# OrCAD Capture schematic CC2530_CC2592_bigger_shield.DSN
size Custom; title: CC2530-CC2592 EM; rev: 2.1
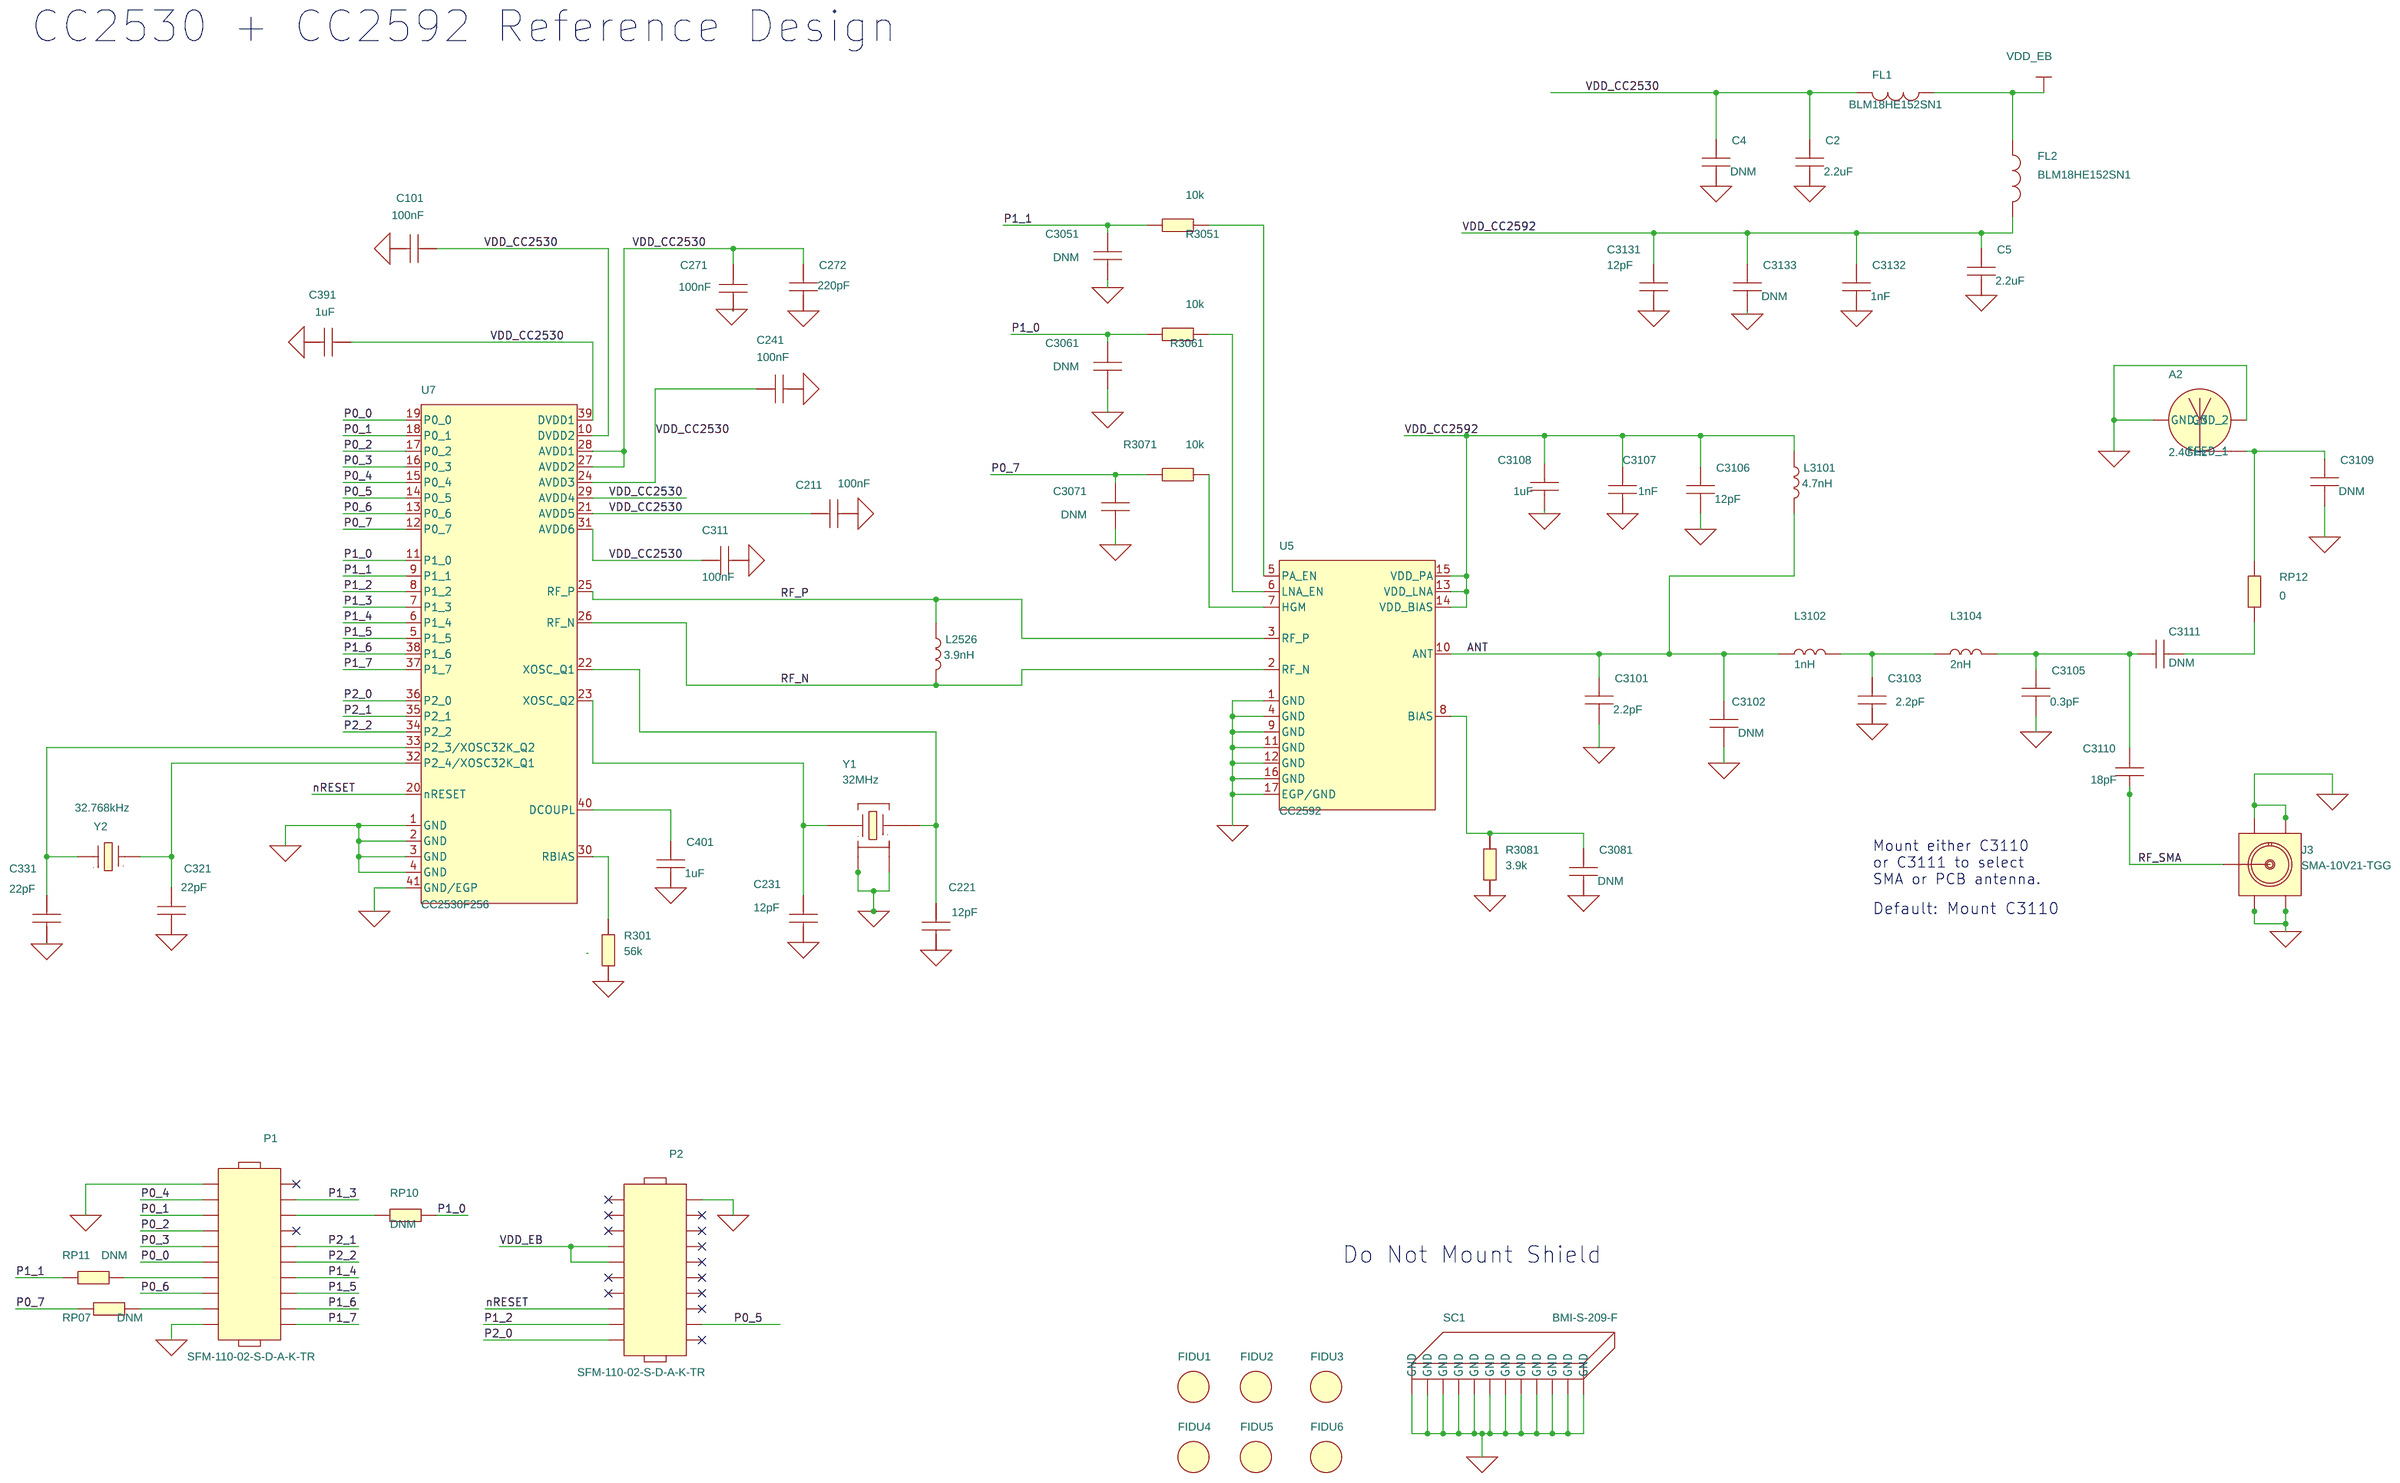
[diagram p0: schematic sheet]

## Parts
A2  2.4GHz  [ANTENNA_DN007AN]
C2  2.2uF  [CAPC1608X90N]
C4  DNM  [CAPC1005X60N]
C5  2.2uF  [CAPC1608X90N]
C101  100nF  [CAPC1005X60N]
C211  100nF  [CAPC1005X60N]
C221  12pF  [CAPC1005X60N]
C231  12pF  [CAPC1005X60N]
C241  100nF  [CAPC1005X60N]
C271  100nF  [CAPC1005X60N]
C272  220pF  [CAPC1005X60N]
C311  100nF  [CAPC1005X60N]
C321  22pF  [CAPC1005X60N]
C331  22pF  [CAPC1005X60N]
C391  1uF  [CAPC1005X60N]
C401  1uF  [CAPC1005X60N]
C3051  DNM  [CAPC1005X60N]
C3061  DNM  [CAPC1005X60N]
C3071  DNM  [CAPC1005X60N]
C3081  DNM  [CAPC1005X60N]
C3101  2.2pF  [CAPC1005X60N]
C3102  DNM  [CAPC1005X60N]
C3103  2.2pF  [CAPC1005X60N]
C3105  0.3pF  [CAPC1005X60N]
C3106  12pF  [CAPC1005X60N]
C3107  1nF  [CAPC1005X60N]
C3108  1uF  [CAPC1005X60N]
C3109  DNM  [CAPC1005X60N]
C3110  18pF  [CAPC1005X60N]
C3111  DNM  [CAPC1005X60N]
C3131  12pF  [CAPC1005X60N]
C3132  1nF  [CAPC1005X60N]
C3133  DNM  [CAPC1005X60N]
FIDU1  FIDU_1MM  [FID100X115]
FIDU2  FIDU_1MM  [FID100X115]
FIDU3  FIDU_1MM  [FID100X115]
FIDU4  FIDU_1MM  [FID100X115]
FIDU5  FIDU_1MM  [FID100X115]
FIDU6  FIDU_1MM  [FID100X115]
FL1  BLM18HE152SN1  [FIL_BLM18HE152SN1DN]
FL2  BLM18HE152SN1  [FIL_BLM18HE152SN1DN]
J3  SMA-10V21-TGG  [HUSTSAN_SMA10V21TGGAN]
L2526  3.9nH  [INDC1005X60N]
L3101  4.7nH  [INDC1005X60N]
L3102  1nH  [INDC1005X60N]
L3104  2nH  [INDC1005X60N]
P1  SFM-110-02-S-D-A-K-TR  [SAMTEC_SFM11002AN]
P2  SFM-110-02-S-D-A-K-TR  [SAMTEC_SFM11002AN]
R301  56k  [RESC1005X40N]
R3051  10k  [RESC1005X40N]
R3061  10k  [RESC1005X40N]
R3071  10k  [RESC1005X40N]
R3081  3.9k  [RESC1005X40N]
RP07  DNM  [RESC1005X40N]
RP10  DNM  [RESC1005X40N]
RP11  DNM  [RESC1005X40N]
RP12  0  [RESC1005X40N]
SC1  BMI-S-209-F  [MECH_BMIS209FN]
U5  CC2592  [QFNFC65P400X400X100-17AN]
U7  CC2530F256  [QFNFC50P600X600X100-41CN]
Y1  32MHz  [XTAL_FA128N]
Y2  32.768kHz  [XTAL_FC12MN]

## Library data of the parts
A2 = ANTENNA_DN007: MECHANIC, 2.4GHz INVERTED F ANTENNA, SMD; AutoDoc File: http://notefied-dynamic-precision.com/DB/Apps/Desktop/Item/Object.aspx?id=85542; Budget Currency: N/A; Budget Price: N/A; Datasheet URL 1: N/A; Datasheet URL 2: http://www.ti.com/lit/an/swru120b/swru120b.pdf; Definied Quality: INDUSTRIAL; Esd Level: HBM 500V; FPLIST: ANTENNA_DN007N,ANTENNA_DN007AN; Last Time Buy: N/A; Lead Time: N/A; MPN: DN007; MPN Status: ACTIVE; MSL: N/A; MTBF: N/A; MTBF Standard: N/A; Manufacturer: TEXAS INSTRUMENTS; Max Oper Temp: +85DEGC; Min Oper Temp: -40DEGC; Mounting Type: SMD; NOTE Status: PREFERRED; Old Footprint: ANTENNA_DN007N,ANTENNA_DN007AN; Packing Size: N/A; Part Number: 13-00347; Part Type: MECHANIC\ANTENNA; Revision: R006; RoHS Status: PART NOT KNOWN; WEIGHT: N/A
C2 C5 = CAPACITOR: CAPACITOR, CERAMIC X5R, 2.2uF, 10V, -20%/+20%, -55DEGC/+85DEGC, 0603, SMD; ALT_SYMBOLS: CAPC1608X90L,CAPC1608X90M; AutoDoc File: http://notefied-dynamic-precision.com/DB/Apps/Desktop/Item/Object.aspx?id=50283; Budget Currency: EUR; Budget Price: 0.067; Datasheet URL 1: http://search.murata.co.jp/Ceramy/image/img/w_hinm/L0005E.pdf; Datasheet URL 2: http://psearch.murata.com/capacitor/product/GRM188R61A225ME34%23.pdf; Definied Quality: INDUSTRIAL; Dielectric Type: X5R; Esd Level: N/A; Last Time Buy: N/A; Lead Time: 20; LifeCycle Status: GROWTH; MPN: GRM188R61A225ME34D; MPN Status: ACTIVE; MSL: 1; MTBF: N/A; MTBF Standard: N/A; Manufacturer: MURATA; Max Oper Temp: +85DEGC; Max Tol: +20%; Min Oper Temp: -55DEGC; Min Tol: -20%; Mounting Type: SMD; NOTE Status: PREFERRED; Old Footprint: CAPC1608X90N,0603; PCB Package: 0603; Packing Size: 4000; Packing Type: TAPE_&_REEL; Part Number: 02-01132; Part Type: CAPACITOR\CERAMIC\0603; Revision: R001; RoHS Status: ROHS_COMPLIANT; Rtd Voltage: 10V; WEIGHT: 0.0063g
C4 C3081 C3102 C3109 C3111 C3133 = CAPACITOR: CAPACITOR, DO NOT MOUNT, 0402, SMD; ALT_SYMBOLS: CAPC1005X60L,CAPC1005X60M; AutoDoc File: https://notefied-dynamic-precision.com/NotefiedWebServices/AutoDocs.aspx?itemid=50472; Old Footprint: CAPC1005X60N,0402; Part Number: 02-01321; Part Type: CAPACITOR\CERAMIC\0402; Revision: R003
C101 C211 C241 C271 C311 = CAPACITOR: CAPACITOR, CERAMIC X7R, 100nF, 6.3V, -10%/+10%, -55DEGC/+125DEGC, 0402, SMD; ALT_SYMBOLS: CAPC1005X60L,CAPC1005X60M; AutoDoc File: http://notefied-dynamic-precision.com/DB/Apps/Desktop/Item/Object.aspx?id=73748; Budget Currency: EUR; Budget Price: 0.004; Datasheet URL 1: http://search.murata.co.jp/Ceramy/image/img/w_hinm/L0005E.pdf; Datasheet URL 2: http://psearch.murata.com/capacitor/product/GRM155R70J104KA01%23.pdf; Definied Quality: INDUSTRIAL; Dielectric Type: X7R; Esd Level: N/A; Last Time Buy: N/A; Lead Time: 6; LifeCycle Status: ACTIVE; MPN: GRM155R70J104KA01D; MPN Status: ACTIVE; MSL: 1; MTBF: N/A; MTBF Standard: N/A; Manufacturer: MURATA; Max Oper Temp: +125DEGC; Max Tol: +10%; Min Oper Temp: -55DEGC; Min Tol: -10%; Mounting Type: SMD; NOTE Status: PREFERRED; Old Footprint: CAPC1005X60N,0402; PCB Package: 0402; Packing Size: 10000; Packing Type: TAPE_&_REEL; Part Number: 02-02323; Part Type: CAPACITOR\CERAMIC\0402; Revision: R000; RoHS Status: ROHS_COMPLIANT; Rtd Voltage: 6.3V; WEIGHT: 0.0016g
C221 C231 C3106 C3131 = CAPACITOR: CAPACITOR, CERAMIC C0G/NP0, 12pF, 50V, -5%/+5%, -55DEGC/+125DEGC, 0402, SMD; ALT_SYMBOLS: CAPC1005X60L,CAPC1005X60M; AutoDoc File: http://notefied-dynamic-precision.com/DB/Apps/Desktop/Item/Object.aspx?id=84867; Budget Currency: EUR; Budget Price: 0.004; Datasheet URL 1: http://search.murata.co.jp/Ceramy/image/img/w_hinm/L0005E.pdf; Datasheet URL 2: http://psearch.murata.com/capacitor/product/GRM1555C1H120JA01%23.pdf; Definied Quality: INDUSTRIAL; Dielectric Type: C0G/NP0; Esd Level: N/A; Last Time Buy: N/A; Lead Time: 10; MPN: GRM1555C1H120JA01D; MPN Status: ACTIVE; MSL: 1; MTBF: N/A; MTBF Standard: N/A; Manufacturer: MURATA; Max Oper Temp: +125DEGC; Max TC: +30PPM/DEGC; Max Tol: +5%; Min Oper Temp: -55DEGC; Min TC: -30PPM/DEGC; Min Tol: -5%; Mounting Type: SMD; NOTE Status: PREFERRED; PCB Package: 0402; Packing Size: 10000; Packing Type: TAPE_&_REEL; Part Number: 02-04168; Part Type: CAPACITOR\CERAMIC\0402; Revision: R000; RoHS Status: ROHS_COMPLIANT; Rtd Voltage: 50V; WEIGHT: 0.0016g
C272 = CAPACITOR: CAPACITOR, CERAMIC C0G/NP0, 220pF, 50V, -5%/+5%, -55DEGC/+125DEGC, 0402, SMD; ALT_SYMBOLS: CAPC1005X60L,CAPC1005X60M; AutoDoc File: http://notefied-dynamic-precision.com/DB/Apps/Desktop/Item/Object.aspx?id=50427; Budget Currency: EUR; Budget Price: 0.005; Datasheet URL 1: http://search.murata.co.jp/Ceramy/image/img/w_hinm/L0005E.pdf; Datasheet URL 2: http://psearch.murata.com/capacitor/product/GRM1555C1H221JA01%23.pdf; Definied Quality: INDUSTRIAL; Dielectric Type: C0G/NP0; Esd Level: N/A; Last Time Buy: N/A; Lead Time: 12; LifeCycle Status: GROWTH; MPN: GRM1555C1H221JA01D; MPN Status: ACTIVE; MSL: 1; MTBF: N/A; MTBF Standard: N/A; Manufacturer: MURATA; Max Oper Temp: +125DEGC; Max Tol: +5%; Min Oper Temp: -55DEGC; Min Tol: -5%; Mounting Type: SMD; NOTE Status: PREFERRED; Old Footprint: CAPC1005X60N,0402; PCB Package: 0402; Packing Size: 10000; Packing Type: TAPE_&_REEL; Part Number: 02-01276; Part Type: CAPACITOR\CERAMIC\0402; Revision: R001; RoHS Status: ROHS_COMPLIANT; Rtd Voltage: 50V; WEIGHT: 0.0016g
C321 C331 = CAPACITOR: CAPACITOR, CERAMIC C0G/NP0, 22pF, 50V, -5%/+5%, -55DEGC/+125DEGC, 0402, SMD; ALT_SYMBOLS: CAPC1005X60L,CAPC1005X60M; AutoDoc File: http://notefied-dynamic-precision.com/DB/Apps/Desktop/Item/Object.aspx?id=86084; Budget Currency: EUR; Budget Price: 0.007; Datasheet URL 1: http://search.murata.co.jp/Ceramy/image/img/w_hinm/L0005E.pdf; Datasheet URL 2: http://psearch.murata.com/capacitor/product/GRM1555C1H220JA01%23.pdf; Definied Quality: INDUSTRIAL; Dielectric Type: C0G/NP0; Esd Level: N/A; Last Time Buy: N/A; Lead Time: 12; MPN: GRM1555C1H220JA01D; MPN Status: ACTIVE; MSL: 1; MTBF: N/A; MTBF Standard: N/A; Manufacturer: MURATA; Max Oper Temp: +125DEGC; Max Tol: +5%; Min Oper Temp: -55DEGC; Min Tol: -5%; Mounting Type: SMD; NOTE Status: PREFERRED; PCB Package: 0402; Packing Size: 10000; Packing Type: TAPE_&_REEL; Part Number: 02-04373; Part Type: CAPACITOR\CERAMIC\0402; Revision: R003; RoHS Status: ROHS_COMPLIANT; Rtd Voltage: 50V; WEIGHT: 0.0016g
C391 C401 C3108 = CAPACITOR: CAPACITOR, CERAMIC X5R, 1uF, 10V, -10%/+10%, -55DEGC/+85DEGC, 0402, SMD; ALT_SYMBOLS: CAPC1005X60L,CAPC1005X60M; AutoDoc File: http://notefied-dynamic-precision.com/DB/Apps/Desktop/Item/Object.aspx?id=74236; Budget Currency: EUR; Budget Price: 0.016; Datasheet URL 1: http://search.murata.co.jp/Ceramy/image/img/w_hinm/L0005E.pdf; Datasheet URL 2: http://psearch.murata.com/capacitor/product/GRM155R61A105KE15%23.pdf; Definied Quality: INDUSTRIAL; Dielectric Type: X5R; Esd Level: N/A; Last Time Buy: N/A; Lead Time: 14; MPN: GRM155R61A105KE15D; MPN Status: ACTIVE; MSL: 1; MTBF: N/A; MTBF Standard: N/A; Manufacturer: MURATA; Max Oper Temp: +85DEGC; Max Tol: +10%; Min Oper Temp: -55DEGC; Min Tol: -10%; Mounting Type: SMD; NOTE Status: PREFERRED; Old Footprint: CAPC1005X60N,0402; PCB Package: 0402; Packing Size: 10000; Packing Type: TAPE_&_REEL; Part Number: 02-02381; Part Type: CAPACITOR\CERAMIC\0402; Revision: R002; RoHS Status: ROHS_COMPLIANT; Rtd Voltage: 10V; WEIGHT: 0.0016g
C3051 C3061 C3071 = CAPACITOR: CAPACITOR, DO NOT MOUNT, 0402, SMD; ALT_SYMBOLS: CAPC1005X60L,CAPC1005X60M; AutoDoc File: http://notefied-dynamic-precision.com/DB/Apps/Desktop/Item/Object.aspx?id=50472; Old Footprint: CAPC1005X60N,0402; Part Number: 02-01321; Part Type: CAPACITOR\CERAMIC\0402; Revision: R003
C3101 = CAPACITOR: CAPACITOR, CERAMIC C0G/NP0, 2.2pF, 50V, -0.25pF/+0.25pF, -55DEGC/+125DEGC, 0402, SMD; ALT_SYMBOLS: CAPC1005X60L,CAPC1005X60M; AutoDoc File: http://notefied-dynamic-precision.com/DB/Apps/Desktop/Item/Object.aspx?id=87251; Budget Currency: EUR; Budget Price: 0.006; Datasheet URL 1: http://search.murata.co.jp/Ceramy/image/img/w_hinm/L0005E.pdf; Datasheet URL 2: http://psearch.murata.com/capacitor/product/GRM1555C1H2R2CA01%23.pdf; Definied Quality: INDUSTRIAL; Dielectric Type: C0G/NP0; Esd Level: N/A; Last Time Buy: N/A; Lead Time: 12; MPN: GRM1555C1H2R2CA01D; MPN Status: ACTIVE; MSL: 1; MTBF: N/A; MTBF Standard: N/A; Manufacturer: MURATA; Max Oper Temp: +125DEGC; Max Tol: +0.25pF; Min Oper Temp: -55DEGC; Min Tol: -0.25pF; Mounting Type: SMD; NOTE Status: PREFERRED; PCB Package: 0402; Packing Size: 10000; Packing Type: TAPE_&_REEL; Part Number: 02-04605; Part Type: CAPACITOR\CERAMIC\0402; Revision: R001; RoHS Status: ROHS_COMPLIANT; Rtd Voltage: 50V; WEIGHT: 0.0016g
C3103 = CAPACITOR: CAPACITOR, CERAMIC C0G/NP0, 2.2pF, 50V, -0.25pF/+0.25pF, -55DEGC/+125DEGC, 0402, SMD; ALT_SYMBOLS: CAPC1005X60L,CAPC1005X60M; AutoDoc File: http://notefied-dynamic-precision.com/DB/Apps/Desktop/Item/Object.aspx?id=87251; Budget Currency: EUR; Budget Price: 0.005; Datasheet URL 1: http://search.murata.co.jp/Ceramy/image/img/w_hinm/L0005E.pdf; Datasheet URL 2: http://psearch.murata.com/capacitor/product/GRM1555C1H2R2CA01%23.pdf; Definied Quality: INDUSTRIAL; Dielectric Type: C0G/NP0; Esd Level: N/A; Last Time Buy: N/A; Lead Time: 12; MPN: GRM1555C1H2R2CA01D; MPN Status: ACTIVE; MSL: 1; MTBF: N/A; MTBF Standard: N/A; Manufacturer: MURATA; Max Oper Temp: +125DEGC; Max Tol: +0.25pF; Min Oper Temp: -55DEGC; Min Tol: -0.25pF; Mounting Type: SMD; NOTE Status: PREFERRED; PCB Package: 0402; Packing Size: 10000; Packing Type: TAPE_&_REEL; Part Number: 02-04605; Part Type: CAPACITOR\CERAMIC\0402; Revision: R001; RoHS Status: ROHS_COMPLIANT; Rtd Voltage: 50V; WEIGHT: 0.0016g
C3105 = CAPACITOR: CAPACITOR, CERAMIC C0G/NP0, 0.3pF, 50V, -0.1pF/+0.1pF, -55DEGC/+125DEGC, 0402, SMD; ALT_SYMBOLS: CAPC1005X60L,CAPC1005X60M; AutoDoc File: http://notefied-dynamic-precision.com/DB/Apps/Desktop/Item/Object.aspx?id=90889; Budget Currency: EUR; Budget Price: 0.014; Datasheet URL 1: http://search.murata.co.jp/Ceramy/image/img/w_hinm/L0005E.pdf; Datasheet URL 2: http://psearch.murata.com/capacitor/product/GRM1555C1HR30BA01%23.pdf; Definied Quality: INDUSTRIAL; Dielectric Type: C0G/NP0; Esd Level: N/A; Last Time Buy: N/A; Lead Time: 10; MPN: GRM1555C1HR30BA01D; MPN Status: ACTIVE; MSL: N/A; MTBF: N/A; MTBF Standard: N/A; Manufacturer: MURATA; Max Oper Temp: +125DEGC; Max TC: +30PPM/DEGC; Max Tol: +0.1pF; Min Oper Temp: -55DEGC; Min TC: -30PPM/DEGC; Min Tol: -0.1pF; Mounting Type: SMD; NOTE Status: PREFERRED; PCB Package: 0402; Packing Size: 10000; Packing Type: TAPE_&_REEL; Part Number: 02-05036; Part Type: CAPACITOR\CERAMIC\0402; Revision: R001; RoHS Status: ROHS_COMPLIANT; Rtd Voltage: 50V; WEIGHT: 0.0016g
C3107 = CAPACITOR: CAPACITOR, CERAMIC C0G/NP0, 1nF, 50V, -5%/+5%, -55DEGC/+125DEGC, 0402, SMD; ALT_SYMBOLS: CAPC1005X60L,CAPC1005X60M; AutoDoc File: http://notefied-dynamic-precision.com/DB/Apps/Desktop/Item/Object.aspx?id=88013; Budget Currency: USD; Budget Price: 0.00589; Datasheet URL 1: N/A; Datasheet URL 2: N/A; Definied Quality: INDUSTRIAL; Dielectric Type: C0G/NP0; Esd Level: N/A; Last Time Buy: N/A; Lead Time: N/A; MPN: CAPACITOR_0402_1nF_C0G/NP0_M_+/-5%_50V; MPN Status: ACTIVE; MSL: N/A; MTBF: N/A; MTBF Standard: N/A; Manufacturer: MANUFACTURER SELECTION; Max Oper Temp: +125DEGC; Max Tol: +5%; Min Oper Temp: -55DEGC; Min Tol: -5%; Mounting Type: SMD; NOTE Status: PREFERRED; PCB Package: 0402; Packing Size: 10000; Packing Type: TAPE_&_REEL; Part Number: 02-04728; Part Type: CAPACITOR\CERAMIC\0402; Revision: R001; RoHS Status: ROHS_COMPLIANT; Rtd Voltage: 50V; WEIGHT: N/A
C3110 = CAPACITOR: CAPACITOR, CERAMIC C0G/NPO, 18pF, 50V, -55DEGC/+125DEGC, 0402, SMD; ALT_SYMBOLS: CAPC1005X60L,CAPC1005X60M; AutoDoc File: http://notefied-dynamic-precision.com/DB/Apps/Desktop/Item/Object.aspx?id=74533; Budget Currency: USD; Budget Price: 0.0051; Datasheet URL 1: http://search.murata.co.jp/Ceramy/image/img/w_hinm/L0005E.pdf; Datasheet URL 2: http://psearch.murata.com/capacitor/product/GRM1555C1H180JA01%23.pdf; Definied Quality: INDUSTRIAL; Dielectric Type: C0G/NP0; Esd Level: N/A; Last Time Buy: N/A; Lead Time: 10; MPN: GRM1555C1H180JA01D; MPN Status: ACTIVE; MSL: 1; MTBF: N/A; MTBF Standard: N/A; Manufacturer: MURATA; Max Oper Temp: +125DEGC; Max Tol: +5%; Min Oper Temp: -55DEGC; Min Tol: -5%; Mounting Type: SMD; NOTE Status: PREFERRED; PCB Package: 0402; Packing Size: 10000; Packing Type: TAPE_&_REEL; Part Number: 02-02407; Part Type: CAPACITOR\CERAMIC\0402; Revision: R002; RoHS Status: ROHS_COMPLIANT; Rtd Voltage: 50V; WEIGHT: 0.0016g
C3132 = CAPACITOR: CAPACITOR, CERAMIC X7R, 1nF, 50V, -5%/+5%, -55DEGC/+125DEGC, 0402, SMD; ALT_SYMBOLS: CAPC1005X60L,CAPC1005X60M; AutoDoc File: http://notefied-dynamic-precision.com/DB/Apps/Desktop/Item/Object.aspx?id=80112; Budget Currency: USD; Budget Price: 0.00589; Datasheet URL 1: N/A; Datasheet URL 2: N/A; Definied Quality: INDUSTRIAL; Dielectric Type: X7R; Esd Level: N/A; Last Time Buy: N/A; Lead Time: N/A; LifeCycle Status: ACTIVE; MPN: CAPACITOR_0402_1nF_X7R_M_+/-5%_50V; MPN Status: ACTIVE; MSL: N/A; MTBF: N/A; MTBF Standard: N/A; Manufacturer: MANUFACTURER SELECTION; Max Oper Temp: +125DEGC; Max Tol: +5%; Min Oper Temp: -55DEGC; Min Tol: -5%; Mounting Type: SMD; NOTE Status: PREFERRED; PCB Package: 0402; Packing Size: 10000; Packing Type: TAPE_&_REEL; Part Number: 02-03019; Part Type: CAPACITOR\CERAMIC\0402; Revision: R001; RoHS Status: ROHS_COMPLIANT; Rtd Voltage: 50V; WEIGHT: N/A
FIDU1-FIDU6 = FIDMARK: FIDUCIAL MARK, ROUND 1MM; AutoDoc File: http://notefied-dynamic-precision.com/DB/Apps/Desktop/Item/Object.aspx?id=74548; Part Number: 19-00111; Part Type: NON_COMPONENT\FIDUCIAL; Revision: R001
FL1 FL2 = FILTER_2PIN: FILTER, EMI, 1500@100MHz, -55DEGC/+125DEGC, 0603, SMD; ALT_SYMBOLS: FIL_BLM18HE152SN1DL,FIL_BLM18HE152SN1DM; AutoDoc File: http://notefied-dynamic-precision.com/DB/Apps/Desktop/Item/Object.aspx?id=85575; Budget Currency: EUR; Budget Price: 0.165; Datasheet URL 1: http://search.murata.co.jp/Ceramy/image/img/w_hinm/L0110E.pdf; Datasheet URL 2: http://search.murata.co.jp/Ceramy/image/img/PDF/ENG/L0110S0101BLM18H.pdf; Definied Quality: INDUSTRIAL; Esd Level: N/A; Impedance: 1500@100MHz; Last Time Buy: N/A; Lead Time: 10; MPN: BLM18HE152SN1D; MPN Status: ACTIVE; MSL: N/A; MTBF: N/A; MTBF Standard: N/A; Manufacturer: MURATA; Max Oper Temp: +125DEGC; Max Tol: +25%; Min Oper Temp: -55DEGC; Min Tol: -25%; Mounting Type: SMD; NOTE Status: PREFERRED; PCB Package: 0603; Packing Size: 4000; Packing Type: TAPE_&_REEL; Part Number: 04-00470; Part Type: FILTER\EMI\0603; Revision: R001; RoHS Status: ROHS_COMPLIANT; Rtd Current: 0.5A; WEIGHT: 0.006g
J3 = CONN_COAX_1+4: CONNECTOR, COAX RF, STRAIGHT, FEMALE, 1 PIN, SMD; ALT_SYMBOLS: HUSTSAN_SMA10V21TGGL,HUSTSAN_SMA10V21TGGM; AutoDoc File: http://notefied-dynamic-precision.com/DB/Apps/Desktop/Item/Object.aspx?id=84956; Budget Currency: USD; Budget Price: 1.21; Datasheet URL 1: N/A; Datasheet URL 2: http://www.hustsan.com.tw/uploaddir/product/SMA-10V21.pdf; Definied Quality: COMMERCIAL; Esd Level: N/A; FPLIST: HUSTSAN_SMA10V21TGGAN,HUSTSAN_SMA10V21TGGN; Last Time Buy: N/A; Lead Time: 5; MPN Status: ACTIVE; MSL: N/A; MTBF: N/A; MTBF Standard: N/A; Manufacturer: HUS-TSAN; Mounting Type: SMD; NOTE Status: PREFERRED; No Of Pos: 1; Old Footprint: HUSTSAN_SMA10V21TGGAN,HUSTSAN_SMA10V21TGGN; Packing Size: 350; Packing Type: TAPE_&_REEL; Part Number: 06-02188; Part Type: CONNECTOR\COAX; Revision: R003; RoHS Status: ROHS_COMPLIANT; WEIGHT: N/A
L2526 = INDUCTOR: INDUCTOR, CHIP, 3.9nH, -0.3nH/+0.3nH, 0.3A, -55DEGC/+125DEGC, 0402, SMD; ALT_SYMBOLS: INDC1005X60L,INDC1005X60M; AutoDoc File: http://notefied-dynamic-precision.com/DB/Apps/Desktop/Item/Object.aspx?id=87734; Budget Currency: EUR; Budget Price: 0.024; Datasheet URL 1: N/A; Datasheet URL 2: http://psearch.murata.com/inductor/product/LQG15HS3N9S02%23.pdf; Definied Quality: INDUSTRIAL; Esd Level: N/A; Frequency: 6GHz; Last Time Buy: N/A; Lead Time: 9; MPN: LQG15HS3N9S02D; MPN Status: ACTIVE; MSL: N/A; MTBF: N/A; MTBF Standard: N/A; Manufacturer: MURATA; Max Oper Temp: +125DEGC; Max Tol: +0.3nH; Min Oper Temp: -55DEGC; Min Tol: -0.3nH; Mounting Type: SMD; NOTE Status: PREFERRED; PCB Package: 0402; Packing Size: 10000; Packing Type: TAPE_&_REEL; Part Number: 03-06630; Part Type: INDUCTOR\CHIP\0402; Resistance: 0.18; Revision: R001; RoHS Status: ROHS_COMPLIANT; Rtd Current: 0.3A; WEIGHT: 0.001g
L3101 = INDUCTOR: INDUCTOR, CHIP, 4.7nH, -0.3nH/+0.3nH, 0.3A, -55DEGC/+125DEGC, 0402, SMD; ALT_SYMBOLS: INDC1005X60L,INDC1005X60M; AutoDoc File: http://notefied-dynamic-precision.com/DB/Apps/Desktop/Item/Object.aspx?id=87735; Budget Currency: EUR; Budget Price: 0.024; Datasheet URL 1: N/A; Datasheet URL 2: http://psearch.murata.com/inductor/product/LQG15HS4N7S02%23.pdf; Definied Quality: INDUSTRIAL; Esd Level: N/A; Frequency: 6GHz; Last Time Buy: N/A; Lead Time: 9; MPN: LQG15HS4N7S02D; MPN Status: NRND; MSL: N/A; MTBF: N/A; MTBF Standard: N/A; Manufacturer: MURATA; Max Oper Temp: +125DEGC; Max Tol: +0.3nH; Min Oper Temp: -55DEGC; Min Tol: -0.3nH; Mounting Type: SMD; NOTE Status: PREFERRED; PCB Package: 0402; Packing Size: 10000; Packing Type: TAPE_&_REEL; Part Number: 03-06631; Part Type: INDUCTOR\CHIP\0402; Resistance: 0.18; Revision: R001; RoHS Status: ROHS_COMPLIANT; Rtd Current: 0.3A; WEIGHT: 0.001g
L3102 = INDUCTOR: INDUCTOR, CHIP, 1nH, -0.3nH/+0.3nH, 0.3A, -55DEGC/+125DEGC, 0402, SMD; ALT_SYMBOLS: INDC1005X60L,INDC1005X60M; AutoDoc File: http://notefied-dynamic-precision.com/DB/Apps/Desktop/Item/Object.aspx?id=87398; Budget Currency: EUR; Budget Price: 0.017; Datasheet URL 1: N/A; Datasheet URL 2: http://psearch.murata.com/inductor/product/LQG15HS1N0S02%23.pdf; Definied Quality: INDUSTRIAL; Esd Level: N/A; Frequency: 10GHz; Last Time Buy: N/A; Lead Time: 9; MPN: LQG15HS1N0S02D; MPN Status: ACTIVE; MSL: N/A; MTBF: N/A; MTBF Standard: N/A; Manufacturer: MURATA; Max Oper Temp: +125DEGC; Max Tol: +0.3nH; Min Oper Temp: -55DEGC; Min Tol: -0.3nH; Mounting Type: SMD; NOTE Status: PREFERRED; PCB Package: 0402; Packing Size: 10000; Packing Type: TAPE_&_REEL; Part Number: 03-06607; Part Type: INDUCTOR\CHIP\0402; Resistance: 0.07; Revision: R001; RoHS Status: ROHS_COMPLIANT; Rtd Current: 0.3A; WEIGHT: 0.001g
L3104 = INDUCTOR: INDUCTOR, CHIP, 2nH, -0.3nH/ +0.3nH, 0.3A, -55DEGC/+125DEGC, 0402, SMD; ALT_SYMBOLS: INDC1005X60L,INDC1005X60M; AutoDoc File: http://notefied-dynamic-precision.com/DB/Apps/Desktop/Item/Object.aspx?id=85431; Budget Currency: EUR; Budget Price: 0.024; Datasheet URL 1: N/A; Datasheet URL 2: http://psearch.murata.com/inductor/product/LQG15HS2N0S02%23.pdf; Definied Quality: INDUSTRIAL; Esd Level: N/A; Frequency: 6GHz; Last Time Buy: N/A; Lead Time: 9; MPN: LQG15HS2N0S02D; MPN Status: NRND; MSL: N/A; MTBF: N/A; MTBF Standard: N/A; Manufacturer: MURATA; Max Oper Temp: +125DEGC; Max Tol: +0.3nH; Min Oper Temp: -55DEGC; Min Tol: -0.3nH; Mounting Type: SMD; NOTE Status: PREFERRED; PCB Package: 0402; Packing Size: 10000; Packing Type: TAPE_&_REEL; Part Number: 03-06525; Part Type: INDUCTOR\CHIP\0402; Revision: R001; RoHS Status: ROHS_COMPLIANT; Rtd Current: 0.3A; WEIGHT: 0.001g
P1 P2 = CONN_HEADER_2X10_P_S: CONNECTOR, HEADER, FEMALE, STRAIGHT, 2 ROWS, 20 PINS, PITCH 1.27mm, SMD; ALT_SYMBOLS: SAMTEC_SFM11002AL,SAMTEC_SFM11002AM; AutoDoc File: http://notefied-dynamic-precision.com/DB/Apps/Desktop/Item/Object.aspx?id=85603; Budget Currency: USD; Budget Price: 3.180; Datasheet URL 1: http://www.samtec.com/documents/webfiles/cpdf/SFM-1XX-XX-XXX-D-XXX-MKT.pdf; Datasheet URL 2: http://www.samtec.com/documents/webfiles/pdf/SFM-SM.PDF; Lead Time: 2; MPN: SFM-110-02-SM-D-A-K-TR; MPN Status: ACTIVE; Manufacturer: SAMTEC; Max Oper Temp: +125DEGC; Min Oper Temp: -55DEGC; Mounting Type: SMD; NOTE Status: PREFERRED; No Of Pos: 20; No Of Rows: 2; Packing Size: 725; Packing Type: TAPE_&_REEL; Part Number: 06-02251; Part Type: CONNECTOR\HEADER; Pitch: 1.27mm; Revision: R001; RoHS Status: ROHS_COMPLIANT; WEIGHT: 0.30875g
R301 = RESISTOR: RESISTOR, THICK FILM, 56k, -5%/+5%, 0.063W, 50V, -55DEGC/+155DEGC, 0402, SMD; ALT_SYMBOLS: RESC1005X40L,RESC1005X40M; AutoDoc File: http://notefied-dynamic-precision.com/DB/Apps/Desktop/Item/Object.aspx?id=47146; Budget Currency: EUR; Budget Price: 0.012; Datasheet URL 1: http://www.vishay.com/docs/20035/dcrcwE3.pdf; Datasheet URL 2: http://www.vishay.com/docs/20035/dcrcwe3.pdf; Definied Quality: INDUSTRIAL; Lead Time: 12; LifeCycle Status: ACTIVE; MPN: CRCW040256K0JNED; MPN Status: ACTIVE; MSL: 1; MTBF: 1.00*10^10; MTBF Standard: CL=90%; Manufacturer: VISHAY; Max Oper Temp: +155DEGC; Max TC: +200PPM; Max Tol: +5%; Min Oper Temp: -55DEGC; Min TC: -200PPM; Min Tol: -5%; Mounting Type: SMD; NOTE Status: PREFERRED; Old Footprint: RESC1005X40N,0402; PCB Package: 0402; Packing Size: 10000; Packing Type: TAPE_&_REEL; Part Number: 01-01262; Part Type: RESISTOR\0402; Resistor Type: THICK FILM; Revision: R001; RoHS Status: ROHS_COMPLIANT; Rtd Power: 0.063W; Rtd Voltage: 50V; WEIGHT: 0.00065g
R3051 R3061 R3071 = RESISTOR: RESISTOR, THICK FILM, 10k, -5%/+5%, 0.063W, 50V, -55DEGC/+155DEGC, 0402, SMD; ALT_SYMBOLS: RESC1005X40L,RESC1005X40M; AutoDoc File: http://notefied-dynamic-precision.com/DB/Apps/Desktop/Item/Object.aspx?id=47128; Budget Currency: EUR; Budget Price: 0.012; Datasheet URL 1: http://www.vishay.com/docs/20035/dcrcwE3.pdf; Datasheet URL 2: http://www.vishay.com/docs/20035/dcrcwe3.pdf; Definied Quality: INDUSTRIAL; Lead Time: 12; LifeCycle Status: ACTIVE; MPN: CRCW040210K0JNED; MPN Status: ACTIVE; MSL: 1; MTBF: 1.00*10^10; MTBF Standard: CL=90%; Manufacturer: VISHAY; Max Oper Temp: +155DEGC; Max TC: +200PPM; Max Tol: +5%; Min Oper Temp: -55DEGC; Min TC: -200PPM; Min Tol: -5%; Mounting Type: SMD; NOTE Status: PREFERRED; Old Footprint: RESC1005X40N,0402; PCB Package: 0402; Packing Size: 10000; Packing Type: TAPE_&_REEL; Part Number: 01-01244; Part Type: RESISTOR\0402; Resistor Type: THICK FILM; Revision: R001; RoHS Status: ROHS_COMPLIANT; Rtd Power: 0.063W; Rtd Voltage: 50V; WEIGHT: 0.00065g
R3081 = RESISTOR: RESISTOR, THICK FILM, 3.9k, -1%/+1%, 0.1W, 50V, -55DEGC/+155DEGC, 0402, SMD; ALT_SYMBOLS: RESC1005X40L,RESC1005X40M; AutoDoc File: http://notefied-dynamic-precision.com/DB/Apps/Desktop/Item/Object.aspx?id=91098; Budget Currency: EUR; Budget Price: 0.005; Datasheet URL 1: N/A; Datasheet URL 2: http://www.industrial.panasonic.com/www-data/pdf/AOA0000/AOA0000CE2.pdf; Definied Quality: INDUSTRIAL; Lead Time: 8; MPN: ERJ2RKF3901X; MPN Status: ACTIVE; MSL: N/A; Manufacturer: PANASONIC INDUSTRIAL; Max Oper Temp: +155DEGC; Max TC: +100PPM/DEGC; Max Tol: +1%; Min Oper Temp: -55DEGC; Min TC: -100PPM/DEGC; Min Tol: -1%; Mounting Type: SMD; NOTE Status: PREFERRED; Old Footprint: RESC1005X60N; PCB Package: 0402; Packing Size: 10000; Packing Type: TAPE_&_REEL; Part Number: 01-17762; Part Type: RESISTOR\0402\PRECISION; Resistor Type: THICK FILM; Revision: R000; RoHS Status: ROHS_COMPLIANT; Rtd Power: 0.1W; Rtd Voltage: 50V; WEIGHT: 0.0008g
RP07 RP10 RP11 = RESISTOR: RESISTOR, THICK FILM, 0, -0/+0.02R, 0.1W, -55DEGC/+155DEGC, 0402, SMD; ALT_SYMBOLS: RESC1005X40L,RESC1005X40M; AutoDoc File: http://notefied-dynamic-precision.com/DB/Apps/Desktop/Item/Object.aspx?id=88969; Budget Currency: N/A; Budget Price: N/A; Datasheet URL 1: N/A; Datasheet URL 2: N/A; Definied Quality: INDUSTRIAL; Esd Level: N/A; Last Time Buy: N/A; Lead Time: N/A; MPN: RESISTOR_0402_0_50V_0.1W_M_DNM; MPN Status: ACTIVE; MSL: N/A; MTBF: N/A; MTBF Standard: N/A; Manufacturer: MANUFACTURER SELECTION; Max Oper Temp: +155DEGC; Min Oper Temp: -55DEGC; Mounting Type: SMD; NOTE Status: PREFERRED; PCB Package: 0402; Packing Size: N/A; Packing Type: N/A; Part Number: 01-17210; Part Type: RESISTOR\0402; Resistance: 0; Resistor Type: THICK FILM; Revision: R001; RoHS Status: PART NOT KNOWN; Rtd Power: 0.1W; Rtd Voltage: 50V; WEIGHT: N/A
RP12 = RESISTOR: RESISTOR, THICK FILM, JUMPER, 0/+0.05R, 0.063W, 50V, -55DEGC/+155DEGC, 0402, SMD; ALT_SYMBOLS: RESC1005X40L,RESC1005X40M; AutoDoc File: http://notefied-dynamic-precision.com/DB/Apps/Desktop/Item/Object.aspx?id=47668; Budget Currency: EUR; Budget Price: 0.004; Datasheet URL 1: http://www.koaspeer.com/pdfs/Appendix_A.pdf; Datasheet URL 2: http://www.koaspeer.com/catimages/Products/RK73Z/RK73Z.pdf; Definied Quality: INDUSTRIAL; Esd Level: N/A; Lead Time: 8; MPN: RK73Z1ETTP; MPN Status: ACTIVE; MSL: 1; MTBF: N/A; MTBF Standard: N/A; Manufacturer: KOA SPEER; Max Oper Temp: +155DEGC; Min Oper Temp: -55DEGC; Mounting Type: SMD; NOTE Status: PREFERRED; Old Footprint: RESC1005X40N,0402; PCB Package: 0402; Packing Size: 10000; Packing Type: TAPE_&_REEL; Part Number: 01-01784; Part Type: RESISTOR\JUMPER\0402; Resistor Type: THICK FILM; Revision: R002; RoHS Status: ROHS_COMPLIANT; Rtd Current: 1A; WEIGHT: N/A
SC1 = SHIELD_COVER_BMI-S-209-F: MACHANIC, STANDARD SURFACE MOUNT SHIELD FRAMES, TWO PIECE, SMD; AutoDoc File: http://notefied-dynamic-precision.com/DB/Apps/Desktop/Item/Object.aspx?id=96685; Datasheet URL 1: N/A; Datasheet URL 2: http://www.lairdtech.com/WorkArea/linkit.aspx?LinkIdentifier=id&ItemID=3331; MPN Status: ACTIVE; Manufacturer: LAIRD; Max Oper Temp: N/A; Min Oper Temp: N/A; Mounting Type: SMD; NOTE Status: PREFERRED; Packing Size: 400; Packing Type: TAPE_&_REEL; Part Number: 13-01034; Part Type: MECHANIC\SHIELD; Revision: R001; RoHS Status: ROHS_COMPLIANT
U5 = IC_RF_CC2592_QFN16_V1: IC, ANALOG, 2.4GHz RF FRONT END, 2V TO 3.7V, QFN16, SMD; ALT_SYMBOLS: QFNFC65P400X400X100-17AL,QFNFC65P400X400X100-17AM; AutoDoc File: http://notefied-dynamic-precision.com/DB/Apps/Desktop/Item/Object.aspx?id=89421; Frequency: 2.4GHz; MPN Status: PRELIMINARY; Manufacturer: TEXAS INSTRUMENTS; Max Oper Temp: +125DEGC; Min Oper Temp: -40DEGC; Mounting Type: SMD; NOTE Status: PREFERRED; PCB Package: QFN16; Part Number: 18-28661; Part Type: IC\ANALOG\RF\MODULATOR; Revision: R002; RoHS Status: ROHS_COMPLIANT; Rtd Voltage: 2V TO 3.7V
U7 = IC_RF_CC2530F256_QFN40: IC, ANALOG, A TRUE SYSTEM-ON-CHIP SOLUTION FOR 2.4GHz IEEE 802.15.4 AND ZigBee APPLICATIONS, 250KB, 2V TO 3.6V, VQFN40, SMD; ALT_SYMBOLS: QFNFC50P600X600X100-41CL,QFNFC50P600X600X100-41CM,QFNFC50P600X600X100-41L,QFNFC50P600X600X100-41M; AutoDoc File: http://notefied-dynamic-precision.com/DB/Apps/Desktop/Item/Object.aspx?id=89055; Budget Currency: USD; Budget Price: 3.20; Datasheet URL 1: http://www.ti.com/lit/er/swrz031/swrz031.pdf; Datasheet URL 2: http://www.ti.com/lit/ds/symlink/cc2530.pdf; Definied Quality: INDUSTRIAL; Esd Level: HBM 2kV; FPLIST: QFNFC50P600X600X100-41CN,QFNFC50P600X600X100-41N; Last Time Buy: N/A; Lead Time: 12; MPN: CC2530F256RHAR; MPN Status: ACTIVE; MSL: 3; MTBF: 3.77*10^8; MTBF Standard: CL=60%,Td=55degC,Ea=0.7eV,Ts=125degC; Manufacturer: TEXAS INSTRUMENTS; Max Oper Temp: +125DEGC; Min Oper Temp: -40DEGC; Mounting Type: SMD; NOTE Status: PREFERRED; Old Footprint: QFNFC50P600X600X100-41CN,QFNFC50P600X600X100-41N; PCB Package: VQFN40; Packing Size: 2500; Packing Type: TAPE_&_REEL; Part Number: 18-28560; Part Type: IC\ANALOG\RF\TRANSCEIVER; Revision: R002; RoHS Status: ROHS_COMPLIANT; Rtd Voltage: 2V TO 3.6V; WEIGHT: 0.1022g
Y1 = XTAL_4: CRYSTAL, OSCILATOR, 32MHz, 10pF, -10PPM/+10PPM, -40DEGC/+85DEGC, SMD; ALT_SYMBOLS: XTAL_FA128L,XTAL_FA128M; AutoDoc File: http://notefied-dynamic-precision.com/DB/Apps/Desktop/Item/Object.aspx?id=85460; Budget Currency: EUR; Budget Price: 0.545; Capacitance: 10pF; Datasheet URL 1: http://www.eea.epson.com/portal/pls/portal/docs/1/1529523.PDF; Datasheet URL 2: http://www.eea.epson.com/portal/pls/portal/docs/1/1529449.PDF; Definied Quality: INDUSTRIAL; Esd Level: N/A; Last Time Buy: N/A; Lead Time: 13; MPN: FA-128 32MHz 10pF 10PPM; MPN Status: ACTIVE; MSL: N/A; MTBF: N/A; MTBF Standard: N/A; Manufacturer: EPSON; Max Oper Temp: +85DEGC; Max Tol: +10PPM; Min Oper Temp: -40DEGC; Min Tol: -10PPM; Mounting Type: SMD; NOTE Status: PREFERRED; PCB Package: SMD; Packing Size: 250; Packing Type: TAPE_&_REEL; Part Number: 12-00422; Part Type: CRYSTAL\OSCILLATOR\MEMS; Revision: R001; RoHS Status: ROHS_COMPLIANT; WEIGHT: N/A
Y2 = XTAL: CRYSTAL, OSCILATOR, 32.768kHz, -20PPM/ + 20PPM, -40DEGC/ +85DEGC, 12.5pF, SMD; ALT_SYMBOLS: XTAL_FC12ML,XTAL_FC12MM; AutoDoc File: http://notefied-dynamic-precision.com/DB/Apps/Desktop/Item/Object.aspx?id=85632; Budget Currency: EUR; Budget Price: 1.16; Capacitance: 12.5pF; Datasheet URL 1: http://www.eea.epson.com/portal/pls/portal/docs/1/1525528.PDF; Datasheet URL 2: http://www.eea.epson.com/portal/pls/portal/docs/1/1525509.PDF; Definied Quality: INDUSTRIAL; Esd Level: N/A; Last Time Buy: N/A; Lead Time: 16; MPN: FC-12M 32.7680KA-A3; MPN Status: ACTIVE; MSL: N/A; MTBF: N/A; MTBF Standard: N/A; Manufacturer: EPSON; Max Oper Temp: +85DEGC; Max Tol: +20PPM; Min Oper Temp: -40DEGC; Min Tol: -20PPM; Mounting Type: SMD; NOTE Status: PREFERRED; Packing Size: 250; Packing Type: TAPE_&_REEL; Part Number: 12-00430; Part Type: CRYSTAL\OSCILLATOR\MEMS; Revision: R001; RoHS Status: ROHS_COMPLIANT; WEIGHT: N/A

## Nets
GND_SIGNAL: A2.2(GND) A2.3(GND) C2.2 C4.2 C5.2 C101.2 C211.2 C221.2 C231.2 C241.2 C271.1 C272.2 C311.2 C321.2 C331.2 C391.2 C401.2 C3051.2 C3061.1 C3071.1 C3081.2 C3101.2 C3102.2 C3103.2 C3105.2 C3106.2 C3107.2 C3108.2 C3109.2 C3131.2 C3132.2 C3133.2 J3.2 J3.3 J3.4 J3.5 P1.1 P1.19 P2.2 R301.1 R3081.1 SC1.1(GND) SC1.2(GND) SC1.3(GND) SC1.4(GND) SC1.5(GND) SC1.6(GND) SC1.7(GND) SC1.8(GND) SC1.9(GND) SC1.10(GND) SC1.11(GND) SC1.12(GND) U5.1(GND) U5.4(GND) U5.9(GND) U5.11(GND) U5.12(GND) U5.16(GND) U5.17(EGP/GND) U7.1(GND) U7.2(GND) U7.3(GND) U7.4(GND) U7.41(GND/EGP) Y1.2 Y1.4
VDD_CC2530: C2.1 C4.1 C101.1 C211.1 C241.1 C271.2 C272.1 C311.1 C391.1 FL1.1 U7.10(DVDD2) U7.21(AVDD5) U7.24(AVDD3) U7.27(AVDD2) U7.28(AVDD1) U7.29(AVDD4) U7.31(AVDD6) U7.39(DVDD1)
VDD_CC2592: C5.1 C3106.1 C3107.1 C3108.1 C3131.1 C3132.1 C3133.1 FL2.1 L3101.1 U5.13(VDD_LNA) U5.14(VDD_BIAS) U5.15(VDD_PA)
VDD_EB: FL1.2 FL2.2 P2.7 P2.9
ANT: C3101.1 C3102.1 L3101.2 L3102.1 U5.10(ANT)
nRESET: P2.15 U7.20(nRESET)
P0_0: P1.11 U7.19(P0_0)
P0_1: P1.5 U7.18(P0_1)
P0_2: P1.7 U7.17(P0_2)
P0_3: P1.9 U7.16(P0_3)
P0_4: P1.3 U7.15(P0_4)
P0_5: P2.18 U7.14(P0_5)
P0_6: P1.15 U7.13(P0_6)
P0_7: C3071.2 R3071.1 RP07.2 U7.12(P0_7)
P1_0: C3061.2 R3061.1 RP10.1 U7.11(P1_0)
P1_1: C3051.1 R3051.1 RP11.2 U7.9(P1_1)
P1_2: P2.17 U7.8(P1_2)
P1_3: P1.4 U7.7(P1_3)
P1_4: P1.14 U7.6(P1_4)
P1_5: P1.16 U7.5(P1)
P1_6: P1.18 U7.38(P1_6)
P1_7: P1.20 U7.37(P1_7)
P2_0: P2.19 U7.36(P2_0)
P2_1: P1.10 U7.35(P2_1)
P2_2: P1.12 U7.34(P2_2)
RF_N: L2526.2 U5.2(RF_N) U7.26(RF_N)
RF_P: L2526.1 U5.3(RF_P) U7.25(RF_P)
RF_SMA: C3110.1 J3.1
N16044212: C3105.1 C3110.2 C3111.1 L3104.2
N16089095: C3081.1 R3081.2 U5.8(BIAS)
N16090178: C331.1 U7.33(P2_3/XOSC32K_Q2) Y2.1
N16090485: C231.1 U7.23(XOSC_Q2) Y1.1
N16090660: C221.1 U7.22(XOSC_Q1) Y1.3
N16094002: C3103.1 L3102.2 L3104.1
N16111864: C321.1 U7.32(P2_4/XOSC32K_Q1) Y2.2
N16112528: R301.2 U7.30(RBIAS)
N16112537: C401.1 U7.40(DCOUPL)
N16121744: P1.17 RP07.1
N16121835: P1.13 RP11.1
N16121857: P1.6 RP10.2
N16154254: R3051.2 U5.5(PA_EN)
N16154263: R3061.2 U5.6(LNA_EN)
N16154275: R3071.2 U5.7(HGM)
N16168655: C3111.2 RP12.2
N16168706: A2.1(FEED) C3109.1 RP12.1

Not connected (* = marked no-connect by the designer): FIDU1 1; FIDU2 1; FIDU3 1; FIDU4 1; FIDU5 1; FIDU6 1; P1 2* 8*; P2 1* 3* 4* 5* 6* 8* 10* 11* 12* 13* 14* 16* 20*

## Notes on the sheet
- CC2530 + CC2592 Reference Design
- Mount either C3110
  or C3111 to select
  SMA or PCB antenna.
- Default: Mount C3110
- Do Not Mount Shield
